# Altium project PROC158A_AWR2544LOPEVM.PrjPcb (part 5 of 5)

## Sheet PROC158A_Temp_Sensor.SchDoc
size 431 x 279 mm; Date: Not shown in title block; ApprovedBy: Not shown in title block; CheckedBy: Not shown in title block; Author: Not shown in title block; CompanyName: Not shown in title block; Engineer: Not shown in title block; Organization: Not shown in title block; Address1: Not shown in title block; Address2: Not shown in title block; Address3: Not shown in title block; Address4: Not shown in title block; DocumentNumber: 24; Revision: Use project parameter SCH_Rev; SheetNumber: 23; SheetTotal: 24; PageSetup: Record=PageOptions¦CenterHorizontal=True¦CenterVertical=True¦PrintScale=1.00¦XCorrection=1.00¦YCorrection=1.00¦PrintKind=0¦BorderSize=5000000¦LeftOffset=0¦BottomOffset=0¦Orientation=2¦PaperLength=1000¦PaperWidth=1000¦Scale=100¦PaperSource=15¦PrintQuality=600¦MediaType=1¦DitherType=10¦PaperKind=Letter¦PrintScaleMode=1
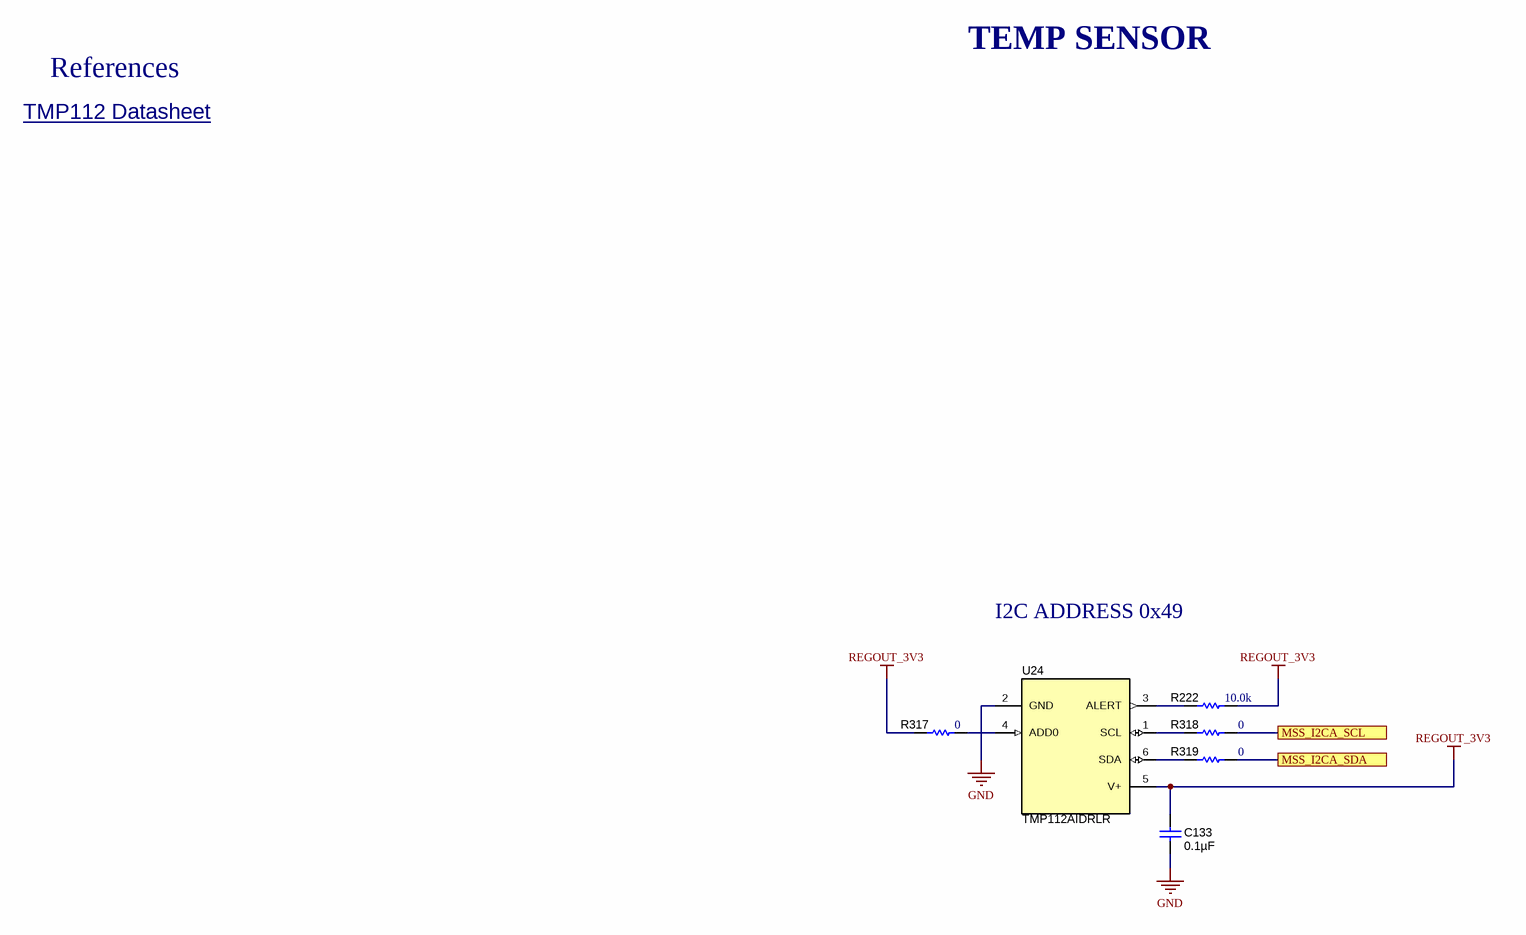
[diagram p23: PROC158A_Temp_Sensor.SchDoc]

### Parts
C133  ValueDisplayed: 0.1µF  [0402L]  (hidden comment: C0402C104K8RACTU)
R222  ValueDisplayed: 10.0k  [0402L]  (hidden comment: CRCW040210K0FKED)
R317  ValueDisplayed: 0  [0201L]  (hidden comment: CRCW02010000Z0ED)
R318  ValueDisplayed: 0  [0201L]  (hidden comment: CRCW02010000Z0ED)
R319  ValueDisplayed: 0  [0201L]  (hidden comment: CRCW02010000Z0ED)
U24  TMP112AIDRLR  [DRL0006A]

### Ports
MSS_I2CA_SCL, MSS_I2CA_SDA

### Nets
GND: C133.2 U24.2(GND)
REGOUT_3V3: C133.1 R222.2 R317.1 U24.5(V+)
MSS_I2CA_SCL: R318.1 ; port MSS_I2CA_SCL
MSS_I2CA_SDA: R319.2 ; port MSS_I2CA_SDA
NetR222_1: R222.1 U24.3(ALERT)
NetR317_2: R317.2 U24.4(ADD0)
NetR318_2: R318.2 U24.1(SCL)
NetR319_1: R319.1 U24.6(SDA)

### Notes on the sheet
- TEMP SENSOR
- References
- TMP112 Datasheet <http://www.ti.com/lit/ds/symlink/tmp112.pdf>
- I2C ADDRESS 0x49

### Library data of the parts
C133 = CMP-0078241-1: CAP, CERM, 0.1 µF, 10 V,+/- 10%, X7R, 0402; Manufacturer: Kemet; TaMin_C: -55°C; Polarized: N; SizeAreaWB_mm2: 3; U/M: EA; Value: 0.1uF; TaMax_C: 125°C; SizeZ_mm: 0.6; SizeX_mm: 1; SizeY_mm: 0.5; Cap_Case: 0402; Value2: 10V; Cap_F: 100nF; AEC Category: Q200
R222 = CMP-0025958-3: RES, 10.0 k, 1%, 0.063 W, AEC-Q200 Grade 0, 0402; Manufacturer: Vishay-Dale; Power_W: 63mW; TempCo: 100 ppm/C; Value_Code: 10k0; Value: 10.0k; EIA_Code: E96; Res_ohm: 10k; SizeX_mm: 1; SizeY_mm: 0.5; SizeZ_mm: 0.6; Value2: 0.063W; AEC Qualified: Y; VDC_V: 50V; AEC Category: Q200; AEC Grade: 0
R317-R319 = CMP-0027008-4: RES, 0, 5%, 0.05 W, 0201; Manufacturer: Vishay-Dale; Power_W: 50mW; TempCo: ppm/C; Value_Code: 0000; Value: 0; EIA_Code: E24; SizeX_mm: 0.6; SizeY_mm: 0.3; SizeZ_mm: 0.26; Value2: 0.05W; SizeArea_mm2: 0.18; AEC Qualified: N; AEC Category: Q200
U24 = CMP-0067397-2: 1.4V-Capable +/-0.5degC Temperature Sensor with Alert Function and I2C/SMBus interface in SOT-563, DRL0006A (SOT-OTHER-6); Alternate PartNumber: TMP112AIDRLT; Alternate Manufacturer: Texas Instruments; Green_Lifecycle: Active; SizeAreaWB_mm2: 6.76; Green_REACh: Passed; U/M: EA; SizeZ_mm: 0.6; SizeX_mm: 1.6; SizeArea_mm2: 2.56; CompType: IC

## Sheet PROC158A_Hardware.SchDoc
size 431 x 279 mm; Date: Not shown in title block; ApprovedBy: Not shown in title block; CheckedBy: Not shown in title block; Author: Not shown in title block; CompanyName: Not shown in title block; Engineer: Not shown in title block; Organization: Not shown in title block; Address1: Not shown in title block; Address2: Not shown in title block; Address3: Not shown in title block; Address4: Not shown in title block; DocumentNumber: 25; Revision: Use project parameter SCH_Rev; SheetNumber: 24; SheetTotal: 24; PageSetup: Record=PageOptions¦CenterHorizontal=True¦CenterVertical=True¦PrintScale=1.00¦XCorrection=1.00¦YCorrection=1.00¦PrintKind=0¦BorderSize=5000000¦LeftOffset=0¦BottomOffset=0¦Orientation=2¦PaperLength=1000¦PaperWidth=1000¦Scale=100¦PaperSource=15¦PrintQuality=600¦MediaType=1¦DitherType=10¦PaperKind=Letter¦PrintScaleMode=1
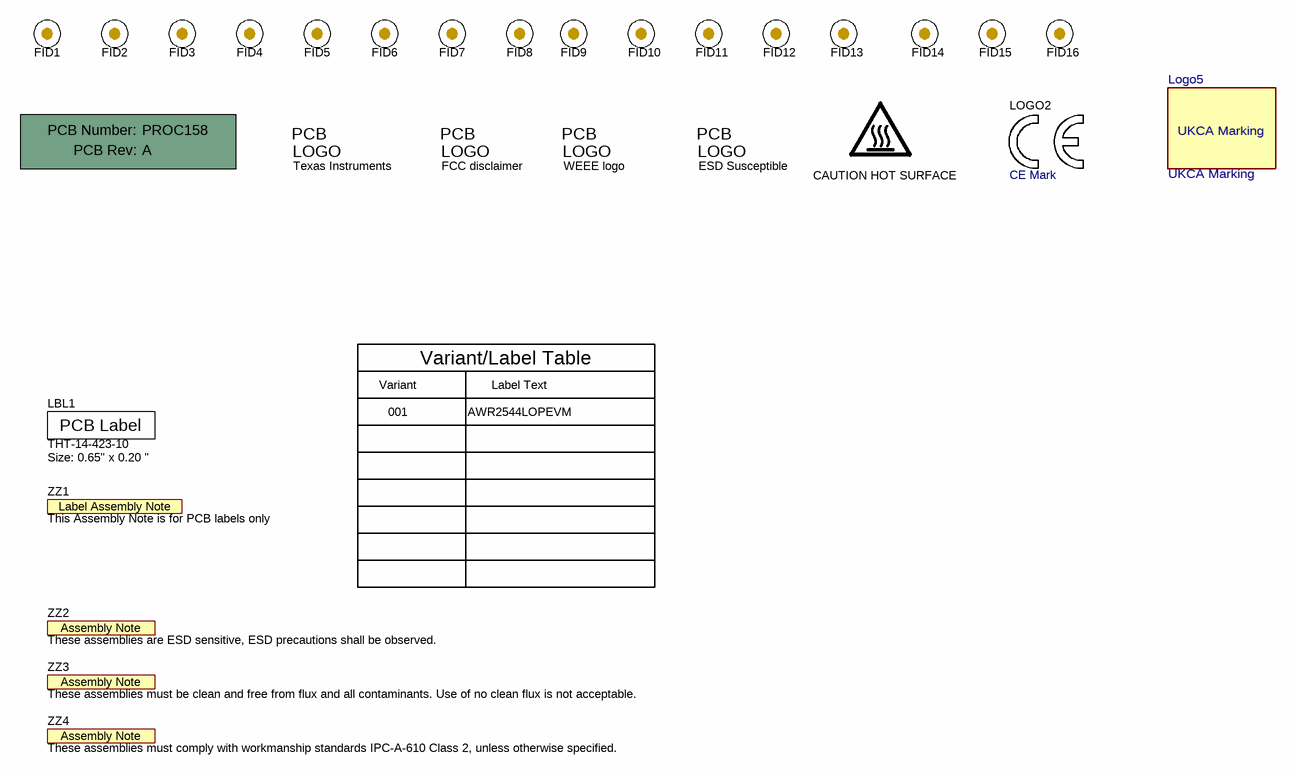
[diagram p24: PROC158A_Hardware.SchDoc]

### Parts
!PCB  Printed Circuit Board  (value not drawn)  (mechanical)
CAUTION_HOT_SURFACE1  CAUTION HOT SURFACE  [IEC_HotSurface_Small]  (no BOM)
ESD_Susceptible1  ESD Susceptible  [ESD_Overlay_Small]  (no BOM)
FID1  Fiducial  [Fiducial10-20]  (value not drawn)  (no BOM)
FID2  Fiducial  [Fiducial10-20]  (value not drawn)  (no BOM)
FID3  Fiducial  [Fiducial10-20]  (value not drawn)  (no BOM)
FID4  Fiducial  [Fiducial10-20]  (value not drawn)  (no BOM)
FID5  Fiducial  [Fiducial10-20]  (value not drawn)  (no BOM)
FID6  Fiducial  [Fiducial10-20]  (value not drawn)  (no BOM)
FID7  Fiducial  [Fiducial10-20]  (value not drawn)  (no BOM)
FID8  Fiducial  [Fiducial10-20]  (value not drawn)  (no BOM)
FID9  Fiducial  [Fiducial10-20]  (value not drawn)  (no BOM)
FID10  Fiducial  [Fiducial10-20]  (value not drawn)  (no BOM)
FID11  Fiducial  [Fiducial10-20]  (value not drawn)  (no BOM)
FID12  Fiducial  [Fiducial10-20]  (value not drawn)  (no BOM)
FID13  Fiducial  [Fiducial10-20]  (value not drawn)  (no BOM)
FID14  Fiducial  [Fiducial10-20]  (value not drawn)  (no BOM)
FID15  Fiducial  [Fiducial10-20]  (value not drawn)  (no BOM)
FID16  Fiducial  [Fiducial10-20]  (value not drawn)  (no BOM)
LBL1  THT-14-423-10  Note: Size: 0.65" x 0.20 "  [Label_650x200]  (no BOM)
Logo1  Texas Instruments  [TI_Stacked_Overlay_Small]  (no BOM)
LOGO2  CE Mark  [CE_Mark_5mm]  (no BOM)
Logo3  FCC disclaimer  [FCC_disclaimer]  (no BOM)
Logo4  WEEE logo  [WEEE_Minimum]  (no BOM)
Logo5  UKCA Marking  [-UKCA_Filled]
ZZ1  This Assembly Note is for PCB labels only  [AssemblyNoteLabel]  (no BOM)
ZZ2  These assemblies are ESD sensitive, ESD precautions shall be observed.  [AssemblyNote]  (no BOM)
ZZ3  These assemblies must be clean and free from flux and all contaminants. Use of no clean flux is not acceptable.  [AssemblyNote]  (no BOM)
ZZ4  These assemblies must comply with workmanship standards IPC-A-610 Class 2, unless otherwise specified.  [AssemblyNote]  (no BOM)

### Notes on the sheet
- Variant
- Variant/Label Table
- Label Text
- 001
- AWR2544LOPEVM

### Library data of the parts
!PCB = CMP-0003618-2: Manufacturer: Any; PartNumber: PROC158
CAUTION_HOT_SURFACE1 = CMP-0074837-1: IEC 61010-1 Hot Surface Warning; Library Reference: IEC_HotSurface; SymbolCreator: a0412235
ESD_Susceptible1 = CMP-0074840-1: ESD Susceptible Symbol; Library Reference: Logo; SymbolCreator: a0412235; Lib Reference: ESD_Susceptible
FID1-FID16 = CMP-0077181-1: Fiducial mark.  There is nothing to buy or mount.
LBL1 = CMP-0003625-1: Thermal Transfer Printable Labels, 0.650" W x 0.200" H - 10,000 per roll; Manufacturer: Brady; CompType: Label; Value: xWR2944EVM
Logo1 = CMP-0074838-1: Texas Instrument Corporate Signature; SymbolCreator: a0412235; Lib Reference: TI_Logo; Library Reference: Logo
LOGO2 = CMP-0074844-1: SymbolCreator: a0412235
Logo3 = CMP-0074847-1: FCC_disclaimer; Library Reference: Logo
Logo4 = CMP-0074769-1
Logo5 = CMP-0093808-1: Manufacturer: Texas Instruments
ZZ1 = CMP-0003616-3
ZZ2 = CMP-0077236-1
ZZ3 = CMP-0077237-1
ZZ4 = CMP-0077238-1

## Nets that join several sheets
1V0: PROC158A_IO_Reference (R133.2), PROC158A_PWR_Reference (U29.A3 U29.A4 U29.M1), PROC158A_Decoupling_Reference (6 pins), PROC158A_PMIC_Reference (R20.2), PROC158A_Current_Sensors (R56.1 R64.1 U22.8)
1V0_ETH: PROC158A_Ethernet_PWR (10 pins), PROC158A_Ethernet_PHY (U15.6 U15.24 U15.31 U15.42)
1V0_FILTERED: PROC158A_PMIC_Reference (6 pins), PROC158A_Current_Sensors (R64.2 R66.1)
1V2: PROC158A_IO_Reference (R315.2), PROC158A_PWR_Reference (13 pins), PROC158A_Decoupling_Reference (9 pins), PROC158A_PMIC_Reference (R70.2), PROC158A_Current_Sensors (R26.1 R30.1 U9.8)
1V2_FILTERED: PROC158A_PMIC_Reference (5 pins), PROC158A_Current_Sensors (R30.2 R32.1)
1V4_APLL: PROC158A_PWR_Reference (U29.H2), PROC158A_Decoupling_Reference (C55.2 C103.1)
1V4_SYNTH: PROC158A_PWR_Reference (U29.H1), PROC158A_Decoupling_Reference (C102.1)
1V8: PROC158A_IO_Reference (R156.2), PROC158A_PWR_Reference (8 pins), PROC158A_Decoupling_Reference (11 pins), PROC158A_PMIC_Reference (R67.2), PROC158A_Current_Sensors (R47.1 R60.1 U11.8)
1V8_FILTERED: PROC158A_PMIC_Reference (5 pins), PROC158A_Current_Sensors (R60.2 R65.1)
2V5_ETH: PROC158A_Ethernet_PWR (8 pins), PROC158A_Ethernet_PHY (U15.3 U15.9)
3V3: PROC158A_PWR_Reference (U29.A12 U29.N18 U29.U12), PROC158A_Decoupling_Reference (C174.2 C175.2 C176.2 C177.2), PROC158A_Current_Sensors (R346.1 R348.1 U12.8)
3V3_VIO: PROC158A_IO_Reference (8 pins), PROC158A_QSPI_Flash_Reference (5 pins), PROC158A_PMIC_Reference (R116.2 R199.2), PROC158A_SOP_Reference (5 pins), PROC158A_PWR_RST_LED (5 pins), PROC158A_VPP_LDO (R409.2), PROC158A_Ethernet_PWR (R295.2), PROC158A_Auto_Ethernet_PHY (5 pins), PROC158A_FTDI_PWR (R73.2), PROC158A_Current_Sensors (R346.2 R352.1)
FTDI_3V3: PROC158A_FTDI_PWR (R182.2), PROC158A_FTDI (17 pins)
GND: PROC158A_IO_Reference (28 pins), PROC158A_PWR_Reference (144 pins), PROC158A_Decoupling_Reference (34 pins), PROC158A_QSPI_Flash_Reference (C1.1 C2.1 U1.4 U1.9), PROC158A_PMIC_Reference (48 pins), PROC158A_3V3_Supply_Reference (15 pins), PROC158A_SOP_Reference (5 pins), PROC158A_PWR_RST_LED (17 pins), PROC158A_VPP_LDO (C145.2 C149.1 U27.2), PROC158A_Ethernet_PWR (27 pins), PROC158A_Ethernet_PHY (13 pins), PROC158A_Ethernet_Magnetics (11 pins), PROC158A_Auto_Ethernet_PHY (28 pins), PROC158A_Auto_Ethernet_conn (15 pins), PROC158A_FTDI_PWR (13 pins), PROC158A_FTDI (31 pins), PROC158A_XDS110 Interface_1A (18 pins), PROC158A_XDS110 Interface_1B (23 pins), PROC158A_JTAG_EMU_Connector (17 pins), PROC158A_Debug_Connector (18 pins), PROC158A_Current_Sensors (9 pins), PROC158A_Temp_Sensor (C133.2 U24.2)
PMIC_LDO_1V0: PROC158A_PMIC_Reference (C51.2 C80.2 U8.11), PROC158A_Auto_Ethernet_PHY (R89.2)
PMICOUT_1V0: PROC158A_PMIC_Reference (8 pins), PROC158A_Auto_Ethernet_PHY (R176.2)
PMICOUT_1V2: PROC158A_PMIC_Reference (7 pins), PROC158A_Auto_Ethernet_PHY (R88.2)
PMICOUT_1V8: PROC158A_IO_Reference (R87.1), PROC158A_PMIC_Reference (7 pins), PROC158A_Ethernet_PWR (C60.1 U17.4 U17.6)
REGOUT_3V3: PROC158A_IO_Reference (C47.2 R416.2 U28.8), PROC158A_PMIC_Reference (L1.1 R199.1 R200.1), PROC158A_3V3_Supply_Reference (7 pins), PROC158A_VPP_LDO (C145.1 U27.1), PROC158A_Ethernet_PWR (C48.1 U16.6), PROC158A_Auto_Ethernet_PHY (R11.1 R50.2), PROC158A_XDS110 Interface_1A (6 pins), PROC158A_XDS110 Interface_1B (20 pins), PROC158A_JTAG_EMU_Connector (6 pins), PROC158A_Debug_Connector (C18.2 R418.2 S2.1 U26.14), PROC158A_Current_Sensors (6 pins), PROC158A_Temp_Sensor (C133.1 R222.2 R317.1 U24.5)
VBAT_INT: PROC158A_3V3_Supply_Reference (5 pins), PROC158A_PWR_RST_LED (C99.1 C101.1 L5.2 R331.2), PROC158A_Auto_Ethernet_conn (R191.2)
VBGAP: PROC158A_PWR_Reference (U29.K1), PROC158A_Decoupling_Reference (C180.1)
VDDC_1: PROC158A_XDS110 Interface_1A (C62.1 C64.2 C74.2 C75.2), PROC158A_XDS110 Interface_1B (U6.87 U6.115)
VDDIO_ETH: PROC158A_Ethernet_PWR (8 pins), PROC158A_Ethernet_PHY (14 pins)
VPP_1P7: PROC158A_PWR_Reference (U29.M18), PROC158A_Decoupling_Reference (C150.2), PROC158A_VPP_LDO (P1.1)
XDSET_1_VBUS: PROC158A_XDS110 Interface_1A (C45.1 R161.2 U10.6), PROC158A_XDS110 Interface_1B (R154.2 R284.2)
AR_NERROUT: PROC158A_IO_Reference (R271.1 U29.D17), PROC158A_PMIC_Reference (R54.1), PROC158A_PWR_RST_LED (DS2.2), PROC158A_Debug_Connector (R379.1)
AR_NRST: PROC158A_IO_Reference (TP4.1 U29.E17), PROC158A_PMIC_Reference (R99.1), PROC158A_PWR_RST_LED (6 pins)
AR_NRST_FTDI: PROC158A_PWR_RST_LED (R268.1), PROC158A_FTDI (R166.2)
AR_NRST_XDS: PROC158A_PWR_RST_LED (R36.1), PROC158A_XDS110 Interface_1B (U6.40)
AR_SOP0_FTDI: PROC158A_SOP_Reference (R308.2), PROC158A_FTDI (R171.2)
AR_SOP1_FTDI: PROC158A_SOP_Reference (R304.2), PROC158A_FTDI (R170.2)
AR_SOP2_FTDI: PROC158A_SOP_Reference (R298.2), PROC158A_FTDI (R169.2)
AR_SYNCIN: PROC158A_IO_Reference (R17.2 U29.C17), PROC158A_Auto_Ethernet_PHY (R61.2 R78.2), PROC158A_Debug_Connector (R115.1)
AR_WRMRST: PROC158A_IO_Reference (R272.1 TP1.1 U29.B17), PROC158A_PWR_RST_LED (D5.2 D9.2), PROC158A_Debug_Connector (R371.1)
AR_WRMRST_FTDI: PROC158A_PWR_RST_LED (R362.1), PROC158A_FTDI (R330.2)
BSS_UARTA_TX: PROC158A_IO_Reference (R232.2 U29.B18), PROC158A_FTDI (R131.1)
CSI2_TX0_LVDS_TX0_N: PROC158A_IO_Reference (U29.K17), PROC158A_Debug_Connector (R366.2)
CSI2_TX0_LVDS_TX0_P: PROC158A_IO_Reference (U29.K18), PROC158A_Debug_Connector (R365.2)
CSI2_TX1_LVDS_TX1_N: PROC158A_IO_Reference (U29.J17), PROC158A_Debug_Connector (R364.2)
CSI2_TX1_LVDS_TX1_P: PROC158A_IO_Reference (U29.J18), PROC158A_Debug_Connector (R363.2)
CSI2_TX2_CLK_LVDS_FRCLK_N: PROC158A_IO_Reference (U29.F17), PROC158A_Debug_Connector (R160.2 R323.2 R349.2)
CSI2_TX2_CLK_LVDS_FRCLK_P: PROC158A_IO_Reference (U29.F18), PROC158A_Debug_Connector (R138.2 R322.2 R345.2)
CSI2_TX3_N: PROC158A_IO_Reference (U29.G17), PROC158A_Debug_Connector (R167.2 R341.2)
CSI2_TX3_P: PROC158A_IO_Reference (U29.G18), PROC158A_Debug_Connector (R164.2 R327.2)
CSI2_TX4_LVDS_CLK_N: PROC158A_IO_Reference (U29.L17), PROC158A_Debug_Connector (R135.2 R361.2)
CSI2_TX4_LVDS_CLK_P: PROC158A_IO_Reference (U29.L18), PROC158A_Debug_Connector (R51.2 R351.2)
EMU_TCK: PROC158A_JTAG_EMU_Connector (R244.1 R354.1 R375.2), PROC158A_Debug_Connector (R422.1)
EMU_TDI: PROC158A_JTAG_EMU_Connector (R356.1 R376.2), PROC158A_Debug_Connector (R423.1)
EMU_TDO: PROC158A_JTAG_EMU_Connector (J19.4 R360.1), PROC158A_Debug_Connector (R425.2)
EMU_TMS: PROC158A_JTAG_EMU_Connector (R358.1 R374.1), PROC158A_Debug_Connector (R424.2)
ETH1_INT_PWDN: PROC158A_IO_Reference (R224.2), PROC158A_Ethernet_PHY (R340.1 U15.44)
ETH1_NRST: PROC158A_IO_Reference (R229.2), PROC158A_Ethernet_PHY (R342.1 U15.43)
ETH2_INT: PROC158A_IO_Reference (R22.1), PROC158A_Auto_Ethernet_PHY (R34.2 U4.2)
ETH2_NRST: PROC158A_IO_Reference (R23.1), PROC158A_Auto_Ethernet_PHY (R46.2 U4.3)
ETH_LED0: PROC158A_Ethernet_PHY (R92.1 R97.2 U15.47), PROC158A_Ethernet_Magnetics (R68.1)
ETH_LED2: PROC158A_Ethernet_PHY (R132.1 R137.2 U15.45), PROC158A_Ethernet_Magnetics (R69.2)
ETH_TRD_N: PROC158A_Auto_Ethernet_PHY (U4.13), PROC158A_Auto_Ethernet_conn (C156.2 R265.1)
ETH_TRD_P: PROC158A_Auto_Ethernet_PHY (U4.12), PROC158A_Auto_Ethernet_conn (C162.1 R270.1)
FTDI_SPI_CLK: PROC158A_FTDI (R144.2), PROC158A_Debug_Connector (U26.16)
FTDI_SPI_CS0: PROC158A_FTDI (R147.2), PROC158A_Debug_Connector (U26.12)
FTDI_SPI_MISO: PROC158A_FTDI (R146.2), PROC158A_Debug_Connector (U26.3)
FTDI_SPI_MOSI: PROC158A_FTDI (R145.2), PROC158A_Debug_Connector (U26.9)
FTDI_USBD_N: PROC158A_FTDI_PWR (J10.2 U21.1), PROC158A_FTDI (U18.7)
FTDI_USBD_P: PROC158A_FTDI_PWR (J10.3 U21.2), PROC158A_FTDI (U18.8)
GPADC1: PROC158A_IO_Reference (C136.2 R316.1 U29.L2), PROC158A_Debug_Connector (R80.1)
GPADC2: PROC158A_IO_Reference (C135.2 R315.1 U29.L1), PROC158A_Debug_Connector (R82.1)
GPADC5: PROC158A_IO_Reference (C131.2 R133.1 U29.N2), PROC158A_Debug_Connector (R91.1)
GPADC6: PROC158A_IO_Reference (U29.M2), PROC158A_Debug_Connector (R94.1)
MCU_CLKOUT: PROC158A_IO_Reference (R165.2), PROC158A_Auto_Ethernet_PHY (R6.1), PROC158A_Debug_Connector (R5.2)
MSS_EPWMA0: PROC158A_IO_Reference (R28.2), PROC158A_Debug_Connector (R81.1)
MSS_EPWMA1: PROC158A_IO_Reference (R19.2), PROC158A_Debug_Connector (R198.1)
MSS_EPWMB0: PROC158A_IO_Reference (R24.2), PROC158A_Debug_Connector (R197.1)
MSS_GPIO_0: PROC158A_IO_Reference (U29.U5), PROC158A_Debug_Connector (R328.1)
MSS_GPIO_1: PROC158A_IO_Reference (U29.U4), PROC158A_Debug_Connector (R329.1)
MSS_GPIO_2: PROC158A_IO_Reference (U29.T4), PROC158A_PWR_RST_LED (R347.2)
MSS_GPIO_3: PROC158A_IO_Reference (R219.2), PROC158A_Debug_Connector (R114.1)
MSS_GPIO_8: PROC158A_IO_Reference (R233.2), PROC158A_PWR_RST_LED (R334.2)
MSS_I2CA_SCL: PROC158A_IO_Reference (R3.1 R276.1 U28.6), PROC158A_PMIC_Reference (R52.1), PROC158A_FTDI (R148.2), PROC158A_Debug_Connector (R390.1), PROC158A_Current_Sensors (R27.2 R33.2 R57.2 R58.2), PROC158A_Temp_Sensor (R318.1)
MSS_I2CA_SDA: PROC158A_IO_Reference (R31.1 R277.1 U28.5), PROC158A_PMIC_Reference (R53.1), PROC158A_FTDI (R149.2 R150.2), PROC158A_Debug_Connector (R391.1), PROC158A_Current_Sensors (R29.2 R35.2 R59.2 R62.2), PROC158A_Temp_Sensor (R319.2)
MSS_MDIO_CLK: PROC158A_IO_Reference (U29.U14), PROC158A_Ethernet_PHY (R369.2), PROC158A_Auto_Ethernet_PHY (R249.1)
MSS_MDIO_DATA: PROC158A_IO_Reference (R280.1 U29.T14), PROC158A_Ethernet_PHY (R413.2), PROC158A_Auto_Ethernet_PHY (R247.1)
MSS_RGMII_RCLK: PROC158A_IO_Reference (U29.U15), PROC158A_Ethernet_PHY (R290.1), PROC158A_Auto_Ethernet_PHY (R234.1)
MSS_RGMII_RCTL: PROC158A_IO_Reference (U29.U16), PROC158A_Ethernet_PHY (R195.1), PROC158A_Auto_Ethernet_PHY (R245.1)
MSS_RGMII_RD0: PROC158A_IO_Reference (U29.T15), PROC158A_Ethernet_PHY (R325.1), PROC158A_Auto_Ethernet_PHY (R237.1)
MSS_RGMII_RD1: PROC158A_IO_Reference (U29.T16), PROC158A_Ethernet_PHY (R336.1), PROC158A_Auto_Ethernet_PHY (R238.1)
MSS_RGMII_RD2: PROC158A_IO_Reference (U29.R16), PROC158A_Ethernet_PHY (R338.1), PROC158A_Auto_Ethernet_PHY (R239.1)
MSS_RGMII_RD3: PROC158A_IO_Reference (U29.U17), PROC158A_Ethernet_PHY (R339.1), PROC158A_Auto_Ethernet_PHY (R240.1)
MSS_RGMII_TCLK: PROC158A_IO_Reference (U29.T17), PROC158A_Ethernet_PHY (R98.1), PROC158A_Auto_Ethernet_PHY (R74.1)
MSS_RGMII_TCTL: PROC158A_IO_Reference (U29.M17), PROC158A_Ethernet_PHY (R101.1), PROC158A_Auto_Ethernet_PHY (R230.1)
MSS_RGMII_TD0: PROC158A_IO_Reference (U29.R17), PROC158A_Ethernet_PHY (R103.1), PROC158A_Auto_Ethernet_PHY (R96.1)
MSS_RGMII_TD1: PROC158A_IO_Reference (U29.P17), PROC158A_Ethernet_PHY (R105.1), PROC158A_Auto_Ethernet_PHY (R100.1)
MSS_RGMII_TD2: PROC158A_IO_Reference (U29.T18), PROC158A_Ethernet_PHY (R121.1), PROC158A_Auto_Ethernet_PHY (R178.1)
MSS_RGMII_TD3: PROC158A_IO_Reference (U29.N17), PROC158A_Ethernet_PHY (R122.1), PROC158A_Auto_Ethernet_PHY (R225.1)
MSS_RS232RX: PROC158A_IO_Reference (R278.1 U29.A11), PROC158A_FTDI (R158.2)
MSS_RS232TX: PROC158A_IO_Reference (R279.1 U29.A16), PROC158A_FTDI (R162.2)
MSS_SPIA_HOSTIRQ: PROC158A_IO_Reference (R18.1 R326.2), PROC158A_FTDI (R151.2 R153.2), PROC158A_Debug_Connector (R320.1)
MSS_SPIB_CLK: PROC158A_IO_Reference (R380.1), PROC158A_Debug_Connector (U26.2)
MSS_SPIB_CS0: PROC158A_IO_Reference (R273.1 U29.T1), PROC158A_Debug_Connector (U26.10)
MSS_SPIB_CS1: PROC158A_IO_Reference (R55.1), PROC158A_Debug_Connector (R215.1)
MSS_SPIB_MISO: PROC158A_IO_Reference (U29.U2), PROC158A_Debug_Connector (U26.5)
MSS_SPIB_MOSI: PROC158A_IO_Reference (R381.1), PROC158A_Debug_Connector (U26.7)
MSS_UARTA_RX: PROC158A_IO_Reference (U29.P1), PROC158A_XDS110 Interface_1B (R129.1)
OSC_CLK_OUT_25: PROC158A_IO_Reference (R95.2 U29.C1), PROC158A_Auto_Ethernet_PHY (R241.1)
OSC_CLKTOP: PROC158A_IO_Reference (R190.2 U29.C2), PROC158A_Auto_Ethernet_PHY (R168.1)
PMIC_EN: PROC158A_PMIC_Reference (R125.1 U8.7), PROC158A_3V3_Supply_Reference (R4.1), PROC158A_Auto_Ethernet_PHY (R12.1)
QSPI_CS: PROC158A_IO_Reference (U29.T6), PROC158A_QSPI_Flash_Reference (R38.1 U1.1)
QSPI_D0: PROC158A_IO_Reference (U29.U8), PROC158A_QSPI_Flash_Reference (R45.2)
QSPI_D1: PROC158A_IO_Reference (U29.U7), PROC158A_QSPI_Flash_Reference (R39.1 R49.1)
QSPI_D2: PROC158A_IO_Reference (U29.U6), PROC158A_QSPI_Flash_Reference (R42.1 R43.1)
QSPI_D3: PROC158A_IO_Reference (U29.T5), PROC158A_QSPI_Flash_Reference (R40.2 R41.1)
QSPI_SCLK: PROC158A_IO_Reference (U29.T7), PROC158A_QSPI_Flash_Reference (R44.2)
SOP0_TDO: PROC158A_IO_Reference (R386.1), PROC158A_SOP_Reference (R310.1), PROC158A_JTAG_EMU_Connector (U23.10)
SOP1_MSS_SPIB_CS2: PROC158A_IO_Reference (U29.T2), PROC158A_SOP_Reference (R305.1), PROC158A_Debug_Connector (R324.1)
SOP2_PMIC_CLK: PROC158A_IO_Reference (R218.2), PROC158A_SOP_Reference (R299.1)
SOP3_MSS_UARTB_TX: PROC158A_IO_Reference (U29.P2), PROC158A_SOP_Reference (R301.1 R303.2), PROC158A_XDS110 Interface_1B (R136.1)
SOP4_MSS_UARTA_TX: PROC158A_IO_Reference (U29.R2), PROC158A_SOP_Reference (R309.1 R312.2), PROC158A_XDS110 Interface_1B (R128.1)
SYNC_CLK: PROC158A_IO_Reference (R104.2), PROC158A_PMIC_Reference (C171.2 R106.1 U8.13)
TCK: PROC158A_IO_Reference (U29.B6), PROC158A_JTAG_EMU_Connector (U23.2)
TD_1_N: PROC158A_Ethernet_PHY (U15.2), PROC158A_Ethernet_Magnetics (J9.10 U13.2 U13.9)
TD_1_P: PROC158A_Ethernet_PHY (U15.1), PROC158A_Ethernet_Magnetics (J9.9 U13.1 U13.10)
TD_2_N: PROC158A_Ethernet_PHY (U15.5), PROC158A_Ethernet_Magnetics (J9.8 U13.5 U13.6)
TD_2_P: PROC158A_Ethernet_PHY (U15.4), PROC158A_Ethernet_Magnetics (J9.7 U13.4 U13.7)
TD_3_N: PROC158A_Ethernet_PHY (U15.8), PROC158A_Ethernet_Magnetics (J9.6 U14.2 U14.9)
TD_3_P: PROC158A_Ethernet_PHY (U15.7), PROC158A_Ethernet_Magnetics (J9.5 U14.1 U14.10)
TD_4_N: PROC158A_Ethernet_PHY (U15.11), PROC158A_Ethernet_Magnetics (J9.4 U14.5 U14.6)
TD_4_P: PROC158A_Ethernet_PHY (U15.10), PROC158A_Ethernet_Magnetics (J9.3 U14.4 U14.7)
TDI: PROC158A_IO_Reference (U29.B8), PROC158A_JTAG_EMU_Connector (U23.5)
TMS: PROC158A_IO_Reference (U29.B5), PROC158A_JTAG_EMU_Connector (U23.7)
TRACE_CLK: PROC158A_IO_Reference (R216.2), PROC158A_JTAG_EMU_Connector (R72.1 R226.1)
TRACE_CTL: PROC158A_IO_Reference (R220.2), PROC158A_JTAG_EMU_Connector (J19.17)
TRACE_DATA0: PROC158A_IO_Reference (R227.1), PROC158A_JTAG_EMU_Connector (J19.19)
TRACE_DATA1: PROC158A_IO_Reference (R231.1), PROC158A_JTAG_EMU_Connector (J19.21)
TRACE_DATA2: PROC158A_IO_Reference (R235.1), PROC158A_JTAG_EMU_Connector (J19.23)
TRACE_DATA3: PROC158A_IO_Reference (R217.1), PROC158A_JTAG_EMU_Connector (J19.25)
TRACE_DATA4: PROC158A_IO_Reference (R221.1), PROC158A_JTAG_EMU_Connector (J19.27)
TRACE_DATA5: PROC158A_IO_Reference (R228.1), PROC158A_JTAG_EMU_Connector (J19.29)
TRACE_DATA6: PROC158A_IO_Reference (R232.1), PROC158A_JTAG_EMU_Connector (J19.31)
TRACE_DATA7: PROC158A_IO_Reference (R236.1), PROC158A_JTAG_EMU_Connector (J19.33)
VPP_EN: PROC158A_IO_Reference (U29.T13), PROC158A_VPP_LDO (R159.1)
XDS_TCK: PROC158A_XDS110 Interface_1B (R387.1), PROC158A_JTAG_EMU_Connector (R353.1)
XDS_TDI: PROC158A_XDS110 Interface_1B (R389.1), PROC158A_JTAG_EMU_Connector (R355.1)
XDS_TDO: PROC158A_XDS110 Interface_1B (U6.37), PROC158A_JTAG_EMU_Connector (R359.1)
XDS_TMS: PROC158A_XDS110 Interface_1B (R388.1), PROC158A_JTAG_EMU_Connector (R357.1)
XDSET_1_D_N: PROC158A_XDS110 Interface_1A (J8.2 U10.1), PROC158A_XDS110 Interface_1B (U6.93)
XDSET_1_D_P: PROC158A_XDS110 Interface_1A (J8.3 U10.2), PROC158A_XDS110 Interface_1B (U6.94)
XDSET_1_ID: PROC158A_XDS110 Interface_1A (J8.4 U10.4), PROC158A_XDS110 Interface_1B (R152.1)
XREF_CLK0: PROC158A_IO_Reference (R25.2), PROC158A_Debug_Connector (R84.1)
XREF_CLK1: PROC158A_IO_Reference (R21.2), PROC158A_Debug_Connector (R90.1)

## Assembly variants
001: not fitted C32 C128 C154 C155 C156 C162 C166 C172 C178 C182 D3 D7 D8 D10 D14 D18 D19 J1 J3 J5 J13 J21 J22 J23 L1 L11 R4 R5 R6 R8 R10 R11 R12 R13 R15 R16 R19 R20 R22 R23 R24 R28 R51 R55 R67 R70 R72 R74 R75 R77 R79 R80 R82 R87 R88 R91 R92 R93 R95 R96 R97 R100 R102 R104 R107 R108 R112 R113 R114 R117 R118 R119 R120 R130 R135 R137 R138 R139 R141 R142 R143 R159 R160 R164 R167 R168 R173 R176 R177 R178 R183 R185 R186 R189 R191 R197 R198 R199 R216 R217 R219 R220 R221 R224 R225 R226 R227 R228 R229 R230 R231 R232 R234 R235 R236 R237 R238 R239 R240 R241 R244 R245 R247 R249 R252 R253 R254 R258 R260 R269 R271 R274 R286 R287 R288 R303 R312 R320 R324 R327 R341 R345 R349 R350 R371 R379 R416 R417 R422 R423 R424 R425 Y6 Y7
